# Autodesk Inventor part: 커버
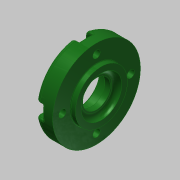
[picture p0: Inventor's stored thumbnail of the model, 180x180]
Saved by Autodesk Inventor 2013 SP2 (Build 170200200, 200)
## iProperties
Created: 2015-11
Part Number: 커버
Material: 알루미늄 6061
Document SubType Name: Modeling
Designer: mduedu
Density: 1 g/cm^3
Author: mduedu
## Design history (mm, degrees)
sketch "스케치1"
  geometry: L1 (-7, 0)-(7, 0); L2 (-7, 0)-(-7, 27); L3 (-7, 27)-(4, 27); L4 (4, 27)-(4, 16); L5 (4, 16)-(7, 16); L6 (7, 16)-(7, 0); 2 further points
  constraints: 12 end point, 3 perpendicular, 2 parallel, 1 coincident, 1 horizontal, 1 midpoint
  dimensions: "d0" = 14 distance of L1.start L1.end; "d1" = 54 diameter of L3 L1; "d2" = 3 distance of L4.end L5.end; "d3" = 32 diameter of L5 L1
revolve "회전1" sketch "스케치1" stored, may be unused: angle "d4" = 90 deg
hole "구멍1" diameter "d7" = 25; stored, may be unused: countersink angle "d11" = 90 deg, drill point angle "d13" = 0 deg; dims "d5" = 10, "d6" = 10, "d8" = 6, "d9" = 4, "d10" = 2, "d12" = 3
hole "구멍2" diameter "d16" = 25; stored, may be unused: countersink angle "d20" = 90 deg, drill point angle "d22" = 0 deg; dims "d17" = 6, "d18" = 4, "d19" = 2, "d21" = 7.7, "d58" = 10, "d59" = 10
hole "구멍3" diameter "d25" = 17; stored, may be unused: countersink angle "d29" = 90 deg, drill point angle "d31" = 0 deg; dims "d23" = 10, "d24" = 10, "d26" = 6, "d27" = 4, "d28" = 2, "d30" = 4.2
chamfer "모따기1" distance "d32" = 0.6; stored, may be unused: second distance "d33" = 2, angle "d34" = 30 deg
fillet "모깎기1" dims "d35" = 0.3
fillet "모깎기2" dims "d36" = 3
fillet "모깎기3" dims "d37" = 3
fillet "모깎기4" dims "d38" = 0.3
sketch "스케치3" dims "d61" = 42
  geometry: C1 r 27 at (0, 0) reference; 2 further points
  constraints: 2 vertical alignment, 1 coincident, 2 other
hole "구멍4" sketch "스케치3" at (0, 21) diameter "d44" = 4.5; stored, may be unused: countersink angle "d48" = 90 deg, drill point angle "d50" = 0 deg; dims "d45" = 6, "d46" = 8, "d47" = 4.6, "d49" = 8
sketch "스케치4"
  geometry: L1 (-4, 5.702)-(-4, 0); L2 (4, 5.702)-(4, 0); A1 r 27 centre (0, -21) between (-4, 5.702) and (4, 5.702) reference; A2 r 4 centre (0, 0) between (-2.824, 2.833) and (2.824, 2.833) reference
  constraints: 4 end point, 4 point on circle, 2 tangent, 2 vertical
extrude "돌출1" cut sketch "스케치4" stored distance "d51" = 0; taper "d52" = 0 deg
fillet "모깎기5" dims "d56" = 0.3
fillet "모깎기6" dims "d57" = 1
node "솔리드1"
pattern_circular "원형 패턴2" dims angle "d64" = 360 deg
pattern_circular "원형 패턴1" dims angle "d54" = 360 deg
